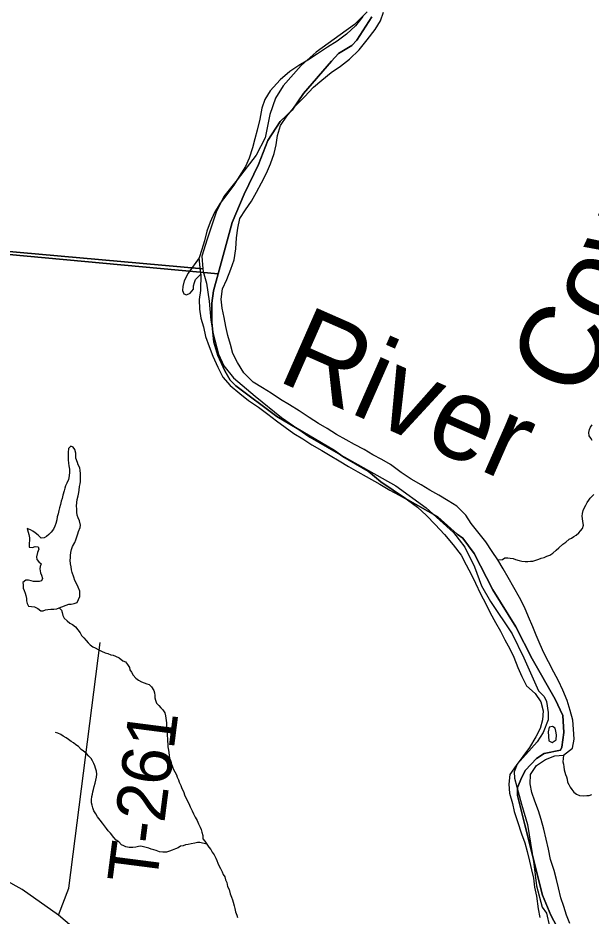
# Model space of a CAD drawing. Extents: x 1310247 to 1664935, y 284496 to 704931.
# Drawn here: x 1514749 to 1518219, y 509226 to 514662 of the extents above; entities that cross this region are included whole.
import ezdxf

# ---------------------------------------------------------------- set-up
doc = ezdxf.new("R2010")
doc.units = 0
for name, color, linetype in [('GM_X_Adjacent_County', 7, 'Continuous'), ('GM_X_Airport_Text_Class_2', 7, 'Continuous'), ('GM_X_City_Street', 7, 'Continuous'), ('GM_X_County', 7, 'Continuous'), ('GM_X_County_Subdivision_Text', 7, 'Continuous'), ('GM_X_Minor_Lake_Text', 7, 'Continuous'), ('GM_X_Minor_River', 7, 'Continuous'), ('GM_X_Minor_River_Text', 7, 'Continuous'), ('GM_X_Township_Subdivision', 7, 'Continuous')]:
    doc.layers.add(name, color=color, linetype=linetype)

msp = doc.modelspace()

# ---------------------------------------------------------------- linework, layer by layer
at = {"layer": 'GM_X_Adjacent_County'}
for points in [[(1516892.3, 514668), (1516801.3, 514527.4), (1516770.6, 514495.1), (1516689.8, 514445.6), (1516647, 514400.5), (1516478.4, 514204.7), (1516408.9, 514102.6), (1516336.1, 514034.3), (1516262.5, 513920.2), (1516206.4, 513775.3), (1516118.6, 513596.1), (1516046.1, 513423.3), (1515960.6, 513113.8), (1512140, 513465.9), (1508014.5, 513835.1)], [(1518068.5, 509057.1), (1517976.5, 509231.4), (1517925.5, 509353.5), (1517819.1, 509778.3), (1517773.2, 509956.4), (1517774.3, 510004.7), (1517800, 510067.6), (1517821.8, 510109.1), (1517890, 510179.6), (1517935.4, 510210.2), (1518034.8, 510230.2), (1518042.3, 510248.9), (1518053.6, 510337.5), (1518048.6, 510439.9), (1518001.5, 510539.5), (1517862.4, 510782.1), (1517764.6, 510976.1), (1517624.9, 511199.6), (1517511.4, 511420.9), (1517443.6, 511513.5), (1517408, 511536.6), (1517291.9, 511641.6), (1517095.4, 511754.3), (1516946.5, 511855.1), (1516870.4, 511918.1), (1516715.5, 512007), (1516665, 512044.5), (1516317.1, 512250.3), (1516068.7, 512435.7), (1516033.4, 512469.4), (1516001.6, 512525.6), (1515959.4, 512618.8), (1515935.2, 512699.7), (1515923.4, 512820.3), (1515924, 512935), (1515932.5, 513009.3), (1515960.6, 513113.8), (1516046.1, 513423.3), (1516118.6, 513596.1), (1516206.4, 513775.3), (1516262.5, 513920.2), (1516336.1, 514034.3), (1516408.9, 514102.6), (1516478.4, 514204.7), (1516647, 514400.5), (1516689.8, 514445.6), (1516770.6, 514495.1), (1516801.3, 514527.4), (1516892.3, 514668)], [(1512140, 513465.9), (1515960.6, 513113.8), (1515932.5, 513009.3), (1515924, 512935), (1515923.4, 512820.3), (1515935.2, 512699.7), (1515959.4, 512618.8), (1516001.6, 512525.6), (1516033.4, 512469.4), (1516068.7, 512435.7), (1516317.1, 512250.3), (1516665, 512044.5), (1516715.5, 512007), (1516870.4, 511918.1), (1516946.5, 511855.1), (1517095.4, 511754.3), (1517291.9, 511641.6), (1517408, 511536.6), (1517443.6, 511513.5), (1517511.4, 511420.9), (1517624.9, 511199.6), (1517764.6, 510976.1), (1517862.4, 510782.1), (1518001.5, 510539.5), (1518048.6, 510439.9), (1518053.6, 510337.5), (1518042.3, 510248.9), (1518034.8, 510230.2), (1517935.4, 510210.2), (1517890, 510179.6), (1517821.8, 510109.1), (1517800, 510067.6), (1517774.3, 510004.7), (1517773.2, 509956.4), (1517819.1, 509778.3), (1517925.5, 509353.5), (1517976.5, 509231.4), (1518068.5, 509057.1)]]:
    msp.add_lwpolyline(points, dxfattribs=at)
at = {"layer": 'GM_X_City_Street'}
msp.add_line((1515857.4, 513111.4), (1515845.9, 513210.6), dxfattribs=at)
for points in [[(1516837.7, 514670), (1516792.8, 514614.6), (1516737.8, 514563.4), (1516681.1, 514520.2), (1516624.4, 514485.1), (1516563.6, 514444), (1516504.9, 514406.8), (1516450.3, 514373.6), (1516395.6, 514336.5), (1516336.7, 514287.3), (1516275.6, 514220.2), (1516244.7, 514168.6), (1516225.8, 514114.8), (1516212.8, 514049), (1516197.7, 513983.1), (1516182.8, 513929.3), (1516170, 513875.4), (1516149, 513813.7), (1516126.1, 513762), (1516089.1, 513702.5), (1516056.2, 513649), (1516013.3, 513593.5), (1515974.4, 513540.1), (1515939.4, 513484.6), (1515912.4, 513424.9), (1515893.6, 513371.2), (1515878.6, 513313.3), (1515861.8, 513259.5), (1515845.9, 513210.6)], [(1516321.4, 513949.2), (1516338.4, 514011), (1516377.4, 514066.4), (1516428.4, 514127.7), (1516483.4, 514184.9), (1516538.4, 514242.1), (1516589.2, 514285.4), (1516646, 514330.5), (1516702.8, 514369.7), (1516757.5, 514412.9), (1516814.5, 514468.1), (1516863.6, 514529.4), (1516912.7, 514592.7), (1516943.5, 514644.3), (1516962.4, 514696)], [(1518090.9, 509180.2), (1518071.6, 509232.6), (1518054.4, 509284.9), (1518037.2, 509337.2), (1518022.1, 509397.5), (1518010.9, 509447.8), (1517995.7, 509502), (1517974.7, 509568.5), (1517961.6, 509630.7), (1517948.5, 509691), (1517933.4, 509751.3), (1517918.3, 509809.6), (1517901.1, 509863.9), (1517878, 509922.3), (1517860.8, 509974.7), (1517851.5, 510026.9), (1517852.4, 510082.9), (1517889.3, 510136.4), (1517944, 510173.6), (1518000.5, 510196.8), (1518052.7, 510200), (1518107.4, 510243.2), (1518116.3, 510297.1), (1518113.2, 510357.2), (1518108.1, 510411.3), (1518092.9, 510469.6), (1518073.8, 510530), (1518048.8, 510592.5), (1518021.6, 510649), (1517994.3, 510701.4), (1517961.2, 510764), (1517934, 510818.5), (1517910.8, 510868.9), (1517887.6, 510925.3), (1517866.3, 510975.7), (1517841.2, 511036.2), (1517816.1, 511094.7), (1517786.9, 511153.2), (1517751.8, 511213.8), (1517716.7, 511274.4), (1517687.4, 511326.9), (1517654.2, 511381.5), (1517620.9, 511432.1), (1517581.8, 511490.8), (1517534.6, 511551.6), (1517493.3, 511602.2), (1517462, 511652.8), (1517406.8, 511707.7), (1517353.2, 511738.6), (1517297.6, 511773.5), (1517244, 511804.4), (1517190.3, 511835.2), (1517130.7, 511870.2), (1517069.3, 511911.2), (1517005.9, 511958.2), (1516952.2, 511989.1), (1516898.6, 512018), (1516844.9, 512048.9), (1516787.3, 512079.8), (1516735.7, 512108.6), (1516678, 512141.5), (1516622.5, 512176.5), (1516568.8, 512207.3), (1516513.3, 512244.2), (1516451.8, 512283.2), (1516394.2, 512320.2), (1516338.6, 512353.1), (1516283.1, 512390), (1516229.5, 512422.9), (1516173.9, 512457.8), (1516116.7, 512514.7), (1516077.6, 512575.4), (1516050.4, 512629.9), (1516035.2, 512686.2), (1516020, 512740.5), (1516008.8, 512794.7), (1515997.6, 512849), (1515986.5, 512905.2), (1515979.3, 512959.4), (1515988.3, 513021.3), (1516013.3, 513079), (1516038.3, 513140.6), (1516059.2, 513198.4), (1516068.3, 513264.3), (1516073.3, 513330.3), (1516080.2, 513390.3), (1516093.2, 513448.1), (1516128, 513499.7), (1516162.9, 513553.2), (1516193.8, 513606.8), (1516224.8, 513664.3), (1516253.8, 513722), (1516278.7, 513779.6), (1516299.7, 513841.4), (1516312.5, 513893.2), (1516321.4, 513949.2)], [(1515845.9, 513210.6), (1515779.4, 513116.6), (1515756.6, 513071), (1515748.1, 513037), (1515745.7, 513013.1), (1515753.4, 512992.9), (1515769.3, 512986.7), (1515791.5, 512996.3), (1515811.9, 513020), (1515812.2, 513040), (1515818.6, 513060), (1515824.9, 513077.9), (1515857.4, 513111.4)], [(1515857.4, 513111.4), (1515853.9, 513011.4), (1515847, 512957.4), (1515848.1, 512899.3), (1515857.3, 512845.1), (1515872.5, 512792.8), (1515885.6, 512734.6), (1515906.7, 512672.2), (1515929.9, 512615.7), (1515958.9, 512547.2), (1515990, 512488.6), (1516033.3, 512437.9), (1516092.7, 512389), (1516146.1, 512346.1), (1516205.6, 512305.1), (1516263.1, 512264.2), (1516314.6, 512223.3), (1516368.1, 512184.4), (1516419.6, 512147.6), (1516473.2, 512114.7), (1516528.7, 512077.8), (1516588.3, 512042.8), (1516640, 512014), (1516693.6, 511981.1), (1516751.1, 511946.2), (1516806.8, 511915.3), (1516858.4, 511886.5), (1516939.9, 511839.1), (1517001.5, 511804.1), (1517057.1, 511773.2), (1517108.7, 511744.4), (1517168.2, 511701.4), (1517223.5, 511650.5), (1517274.8, 511595.6), (1517331.9, 511534.7), (1517385.1, 511473.8), (1517432.2, 511411), (1517463.4, 511352.4), (1517494.5, 511291.9), (1517519.8, 511241.4), (1517550.8, 511176.9), (1517581.9, 511116.3), (1517609.2, 511061.8), (1517640.3, 511003.3), (1517671.6, 510950.7), (1517696.8, 510898.3), (1517728, 510843.7), (1517751.3, 510793.3), (1517776.3, 510730.9), (1517799.6, 510676.4), (1517828.7, 510619.9), (1517880.1, 510573.1), (1517915.4, 510522.5), (1517928.6, 510468.2), (1517925.7, 510414.2), (1517910.9, 510362.3), (1517886, 510310.7), (1517847, 510247.2), (1517806, 510191.8), (1517765.1, 510138.4), (1517728.2, 510082.9), (1517721.3, 510024.9), (1517726.4, 509970.8), (1517743.5, 509908.4), (1517754.7, 509858.2), (1517773.8, 509797.8), (1517798.7, 509723.4), (1517817.9, 509669), (1517833.1, 509616.7), (1517846.2, 509558.4), (1517859.5, 509506.2), (1517870.7, 509455.9), (1517877.9, 509401.8), (1517889.1, 509347.5), (1517899.9, 509269.3), (1517909.1, 509217.1)], [(1518008, 510292.8), (1518010.5, 510322.8), (1518006.8, 510344.8), (1518001.1, 510362.9), (1517985.2, 510373.2), (1517965.1, 510369.5), (1517958.7, 510341.6)], [(1517958.7, 510341.6), (1517963.8, 510287.4), (1517983.7, 510277.1), (1518008, 510292.8)]]:
    msp.add_lwpolyline(points, dxfattribs=at)
at = {"layer": 'GM_X_County'}
for points in [[(1516863.5, 514699.1), (1516786.2, 514622.4), (1516701.2, 514559.9), (1516555.4, 514454.5), (1516464, 514374.1), (1516355.9, 514250), (1516308.6, 514176.9), (1516274.9, 514077.4), (1516246.5, 513936), (1516190.7, 513831), (1516076.1, 513681), (1515996.4, 513580.4), (1515948.8, 513485.3), (1515893.9, 513322.2), (1515862.2, 513220.8), (1515868.9, 513142.7), (1512143.7, 513477.1), (1512614.9, 519095.5)], [(1512143.7, 513477.1), (1515868.9, 513142.7), (1515870.6, 513126.7), (1515891.4, 513056.4), (1515907.5, 512948.1), (1515917.5, 512832), (1515932, 512749.7), (1515963.9, 512627.2), (1515996.7, 512556.7), (1516053.4, 512483.7), (1516185.4, 512373.4), (1516345.1, 512242.7), (1516517, 512123.8), (1516673.4, 512033.1), (1517037.8, 511830.8), (1517221.4, 511697.7), (1517386.8, 511546.9), (1517455.3, 511459.7), (1517513.1, 511338.8), (1517555.1, 511224.1), (1517609.5, 511129.1), (1517742.1, 510934.9), (1517811.5, 510789.7), (1517902.1, 510590.2), (1517935.4, 510555.6), (1517948.9, 510525.4), (1517959.8, 510457.3), (1517959, 510413.3), (1517929.7, 510337.8), (1517892.7, 510280.4), (1517772.4, 510144.6), (1517753.6, 510098.9), (1517754.9, 510060.9), (1517798.2, 509904.2), (1517834, 509779.6), (1517873.9, 509543), (1517889.6, 509408.8), (1517923.4, 509280.2), (1517948.7, 509243.8), (1517967.3, 509163.5)]]:
    msp.add_lwpolyline(points, dxfattribs=at)
at = {"layer": 'GM_X_County_Subdivision_Text'}
for points in [[(1514993.8, 509232.4), (1515057.3, 509395.1), (1515246.7, 510882.2)], [(1515971.3, 508360.6), (1515626.3, 508539), (1515525.2, 508648.2), (1515296.7, 508931.8), (1515170.5, 509081.5), (1514993.8, 509232.4), (1514775.4, 509387.2), (1514493.6, 509542), (1514144.2, 509694.9), (1513563.6, 510050.2), (1513217.2, 510311.2), (1513052.4, 510446.2), (1512736.8, 510722.1), (1512721.9, 510736)]]:
    msp.add_lwpolyline(points, dxfattribs=at)
at = {"layer": 'GM_X_Minor_River'}
for points in [[(1515108.6, 511124.2), (1515123.5, 511160.1), (1515123.9, 511176.1), (1515124.3, 511192.2), (1515114.7, 511216.5), (1515103.2, 511238.8), (1515093.5, 511257), (1515087.9, 511277.2), (1515076.5, 511305.5), (1515072.8, 511321.7), (1515071.2, 511339.8), (1515067.6, 511357.9), (1515066.1, 511380.1), (1515066.4, 511394.1), (1515066.7, 511408.2), (1515069.2, 511426.2), (1515073.6, 511444.2), (1515080, 511462.2), (1515092.7, 511486), (1515099.1, 511504), (1515112, 511539.9), (1515116.3, 511553.9), (1515124.9, 511577.8), (1515127.3, 511591.8), (1515121.8, 511618.1), (1515114.2, 511636.3), (1515108.5, 511652.5), (1515104.9, 511670.6), (1515105.3, 511690.7), (1515103.7, 511706.8), (1515106.2, 511728.8), (1515108.6, 511746.9), (1515113.1, 511768.9), (1515117.6, 511788.9), (1515119.9, 511802.9), (1515122.4, 511825), (1515124.9, 511843), (1515127.2, 511857), (1515127.6, 511875.1), (1515127.9, 511889.1), (1515128.3, 511905.2), (1515126.7, 511923.3), (1515123, 511939.4), (1515113.4, 511957.7), (1515109.7, 511971.8), (1515100.2, 511998.1), (1515100.5, 512012.1), (1515098.9, 512028.2), (1515093.3, 512050.5), (1515083.6, 512064.7), (1515069.6, 512071), (1515055.2, 512055.2), (1515052.6, 512031.1), (1515053.6, 511986.9), (1515055.2, 511966.8), (1515056.8, 511950.7), (1515060.4, 511930.5), (1515062, 511912.4), (1515059.5, 511890.4), (1515055, 511868.4), (1515044.4, 511846.5), (1515038, 511830.5), (1515033.7, 511816.5), (1515029.3, 511800.5), (1515020.6, 511772.6), (1515016.1, 511752.6), (1515011.7, 511736.6), (1515007.3, 511716.6), (1515000.8, 511696.6), (1514996.4, 511680.6), (1514991.9, 511660.6), (1514987.5, 511642.6), (1514985.1, 511624.6), (1514978.5, 511602.6), (1514972.1, 511586.7), (1514963.6, 511566.7), (1514951.1, 511548.9), (1514936.7, 511535.1), (1514922.4, 511523.3), (1514908.1, 511515.5), (1514890, 511513.8), (1514872.3, 511532.2), (1514854.4, 511544.6), (1514838.5, 511555), (1514824.6, 511563.2), (1514804.7, 511571.6), (1514810.2, 511549.5), (1514816, 511535.3), (1514819.5, 511515.1), (1514819.2, 511501.1), (1514816.7, 511481), (1514816.3, 511459), (1514836.3, 511456.6), (1514852.6, 511462.3), (1514870.6, 511460), (1514876.3, 511445.8), (1514867.8, 511425.9), (1514861.2, 511399.9), (1514862.9, 511383.8), (1514876.6, 511369.5), (1514890.4, 511357.2)], [(1514890.4, 511357.2), (1514884.1, 511341.2), (1514881.7, 511327.2), (1514885.2, 511303), (1514890.9, 511288.9), (1514898.5, 511268.6), (1514892.2, 511254.7), (1514878, 511250.9), (1514861.9, 511251.2), (1514843.8, 511251.6), (1514829.8, 511255.8), (1514813.7, 511258.1), (1514797.6, 511258.4), (1514779.2, 511244.7), (1514780.9, 511230.6), (1514780.4, 511210.5), (1514786.2, 511196.4), (1514793.8, 511180.2), (1514797.6, 511166), (1514801.2, 511147.9), (1514800.8, 511133.8), (1514804.5, 511117.7), (1514812.2, 511101.5), (1514830.3, 511099.1), (1514850.3, 511096.8), (1514870.3, 511088.4), (1514888.1, 511074), (1514902.2, 511073.7), (1514916.4, 511079.5), (1514930.5, 511081.2), (1514948.7, 511082.9), (1514966.8, 511082.6), (1514985, 511086.3), (1514998, 511091.8)], [(1514998, 511091.8), (1515058.1, 511113.1), (1515072.2, 511114.8), (1515090.4, 511118.5), (1515108.6, 511124.2)]]:
    msp.add_lwpolyline(points, dxfattribs=at)
at = {"layer": 'GM_X_Minor_River_Text'}
for points in [[(1518226.9, 512103.5), (1518217.1, 512117.8), (1518207.4, 512132), (1518205.8, 512152.1), (1518210.2, 512170.1), (1518216.6, 512184.1), (1518227, 512200)], [(1517654.2, 511381.5), (1517683.2, 511384.4), (1517697.5, 511394.1), (1517715.6, 511393.8), (1517729.7, 511391.5), (1517747.7, 511389.2), (1517761.7, 511384.9), (1517783.7, 511378.5), (1517799.7, 511374.2), (1517819.8, 511371.8), (1517835.9, 511371.5), (1517852, 511373.2), (1517866.2, 511375), (1517884.4, 511380.7), (1517902.7, 511386.4), (1517916.9, 511392.1), (1517935.1, 511395.8), (1517951.4, 511403.6), (1517969.7, 511411.3), (1517988, 511423), (1518008.6, 511440.7), (1518025, 511454.4), (1518047.6, 511476.1), (1518066, 511489.8), (1518086.6, 511507.5), (1518100.8, 511513.3), (1518115.1, 511523.1), (1518129.4, 511530.9), (1518145.8, 511544.6), (1518156.2, 511558.5), (1518166.6, 511572.4), (1518173, 511592.3), (1518169.5, 511614.5), (1518167.9, 511632.6), (1518166.2, 511646.7), (1518166.6, 511662.8), (1518171, 511680.8), (1518177.4, 511694.7), (1518187.8, 511712.6), (1518196.3, 511728.5), (1518206.6, 511742.4), (1518215, 511756.3), (1518235.6, 511778)], [(1514998, 511091.8), (1515013.4, 511077.6), (1515016.7, 511063.6), (1515020.3, 511045.5), (1515030, 511029.2), (1515047.7, 511012.8), (1515063.5, 510998.5), (1515079.4, 510990.1), (1515097.2, 510975.8), (1515110.9, 510959.4), (1515126.6, 510941.1), (1515134.3, 510924.9), (1515148.1, 510910.5), (1515161.8, 510894.2), (1515173.6, 510880), (1515187.4, 510867.6), (1515203.2, 510855.3), (1515217.2, 510849), (1515235, 510838.6), (1515255, 510830.2), (1515276.9, 510819.8), (1515292.9, 510815.5), (1515310.8, 510807.1), (1515324.9, 510804.9), (1515340.8, 510798.5), (1515362.7, 510788.1), (1515384.5, 510771.6), (1515400.5, 510765.3), (1515412.2, 510749), (1515423.9, 510730.7), (1515427.6, 510716.6), (1515437.3, 510702.4), (1515447, 510684.1), (1515462.7, 510665.8), (1515478.5, 510653.4), (1515496.4, 510643), (1515514.4, 510638.7), (1515530.3, 510632.4), (1515544.3, 510628.1), (1515558.1, 510613.8), (1515571.7, 510591.5), (1515575.4, 510577.3), (1515577, 510561.2), (1515578.7, 510547.1), (1515582.4, 510533), (1515588.1, 510514.8), (1515601.8, 510500.5), (1515613.6, 510486.2), (1515627.4, 510473.9), (1515639.1, 510455.6), (1515642.7, 510437.5), (1515644.4, 510423.4), (1515646.1, 510409.3), (1515647.8, 510395.2), (1515649.4, 510379.1), (1515649, 510361), (1515650.7, 510345), (1515652.4, 510330.9), (1515652, 510316.8), (1515653.7, 510300.7), (1515655.3, 510284.6), (1515656.9, 510266.5), (1515656.6, 510250.4), (1515660.2, 510230.3), (1515661.9, 510216.2), (1515665.5, 510198), (1515667.1, 510179.9), (1515672.7, 510163.8), (1515676.5, 510149.6), (1515682.2, 510135.5), (1515689.8, 510117.2), (1515699.5, 510099), (1515709.1, 510080.7), (1515712.8, 510066.6), (1515720.5, 510050.4), (1515726.2, 510036.2), (1515735.8, 510016), (1515741.5, 509997.8), (1515751.1, 509979.5), (1515760.6, 509953.3), (1515768.3, 509939), (1515774, 509924.9), (1515783.7, 509906.6), (1515791.3, 509886.4), (1515804.8, 509862.1), (1515812.5, 509845.8), (1515822.1, 509825.6), (1515833.7, 509805.3), (1515843.4, 509785), (1515853, 509764.8), (1515858.7, 509750.6), (1515862.3, 509734.5), (1515867.9, 509714.3), (1515869.5, 509694.1), (1515881.2, 509679.9), (1515892.9, 509661.6), (1515904.6, 509643.3), (1515916.3, 509629), (1515926, 509612.8), (1515937.7, 509596.5), (1515947.3, 509576.2)], [(1515892.9, 509661.6), (1515850.9, 509672.4), (1515836.7, 509670.7), (1515820.6, 509666.9), (1515798.3, 509663.3), (1515780.1, 509659.6), (1515764, 509657.9), (1515749.8, 509652.2), (1515733.6, 509648.4), (1515719.3, 509638.7), (1515703, 509632.9), (1515682.7, 509625.3), (1515666.5, 509619.5), (1515648.2, 509613.8), (1515626.1, 509612.2), (1515606, 509614.6), (1515586, 509623), (1515572.1, 509627.3), (1515556.1, 509631.6), (1515542.1, 509637.9), (1515526, 509640.2), (1515510, 509644.5), (1515494, 509648.8), (1515479.9, 509647.1), (1515463.7, 509643.3), (1515445.6, 509641.7), (1515423.4, 509642.1), (1515403.3, 509644.5), (1515389.4, 509650.7), (1515375.4, 509657), (1515359.8, 509675.4), (1515343.9, 509685.7), (1515330.2, 509702), (1515308.6, 509728.5), (1515294.8, 509742.8), (1515285.1, 509757.1), (1515273.3, 509771.4), (1515261.6, 509787.6), (1515246, 509806), (1515230.3, 509826.4), (1515220.7, 509844.6), (1515209, 509862.9), (1515203.4, 509881.1), (1515197.7, 509897.3), (1515194, 509911.4), (1515194.4, 509929.5), (1515196.9, 509949.5), (1515201.2, 509963.5), (1515203.5, 509977.5), (1515205.9, 509991.5), (1515210.3, 510009.5), (1515216.8, 510029.5), (1515221.2, 510049.5), (1515225.7, 510067.5), (1515226.1, 510085.6), (1515224.5, 510103.7), (1515218.9, 510121.9), (1515215.2, 510136), (1515209.4, 510150.1), (1515199.7, 510166.4), (1515192, 510180.6), (1515178.2, 510192.9), (1515164.5, 510209.2), (1515146.7, 510223.6), (1515132.8, 510233.9), (1515115.1, 510252.3), (1515099.2, 510262.6), (1515085.4, 510275), (1515071.5, 510283.2), (1515055.7, 510295.6), (1515041.8, 510303.9), (1515023.9, 510314.2), (1515008, 510324.6), (1514990.1, 510332.9), (1514976.1, 510337.2)], [(1518052.7, 510200), (1518048.1, 510160.5), (1518051.8, 510146.3), (1518055.5, 510130.2), (1518057.1, 510112.1), (1518060.8, 510097.9), (1518064.5, 510083.8), (1518070.2, 510069.6), (1518073.9, 510055.5), (1518077.5, 510037.4), (1518085.3, 510023.2), (1518093, 510007), (1518102.7, 509992.7), (1518114.4, 509976.5), (1518132.2, 509964.1), (1518150.2, 509955.7), (1518174.3, 509953.2), (1518194.4, 509954.9), (1518208.6, 509956.6), (1518224.8, 509962.4)], [(1515947.3, 509576.2), (1515953.1, 509562.1), (1515958.7, 509545.9), (1515968.4, 509527.6), (1515976.1, 509513.4), (1515985.7, 509493.2), (1515991.4, 509477), (1516001.1, 509462.8), (1516006.8, 509444.6), (1516014.5, 509428.4), (1516017.9, 509404.2), (1516027.6, 509386), (1516035.1, 509361.7), (1516042.7, 509341.5), (1516048.4, 509325.3), (1516052.1, 509311.2), (1516057.6, 509289), (1516063.3, 509272.8), (1516066.9, 509252.7), (1516074.5, 509232.4), (1516078.2, 509218.3)]]:
    msp.add_lwpolyline(points, dxfattribs=at)

# ---------------------------------------------------------------- texts
at = {"layer": 'GM_X_Airport_Text_Class_2'}
msp.add_text('River', height=499.97, rotation=336.2415, dxfattribs=at).set_placement((1516307.8, 512470.3))
at = {"layer": 'GM_X_Minor_Lake_Text'}
msp.add_text('Cowen', height=499.99, rotation=65.1859, dxfattribs=at).set_placement((1518162.4, 512340.5))
at = {"layer": 'GM_X_Township_Subdivision'}
msp.add_text('T-261', height=300, rotation=82.6653, dxfattribs=at).set_placement((1515587, 509410.1))

doc.saveas('drawing.dxf')
